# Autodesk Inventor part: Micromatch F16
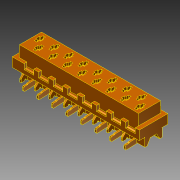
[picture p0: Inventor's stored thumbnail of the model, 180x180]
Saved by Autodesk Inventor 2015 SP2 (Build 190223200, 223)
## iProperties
Created: 2015-08
Part Number: Micromatch F16
Material: Allgemein
Document SubType Name: Modeling
Designer: rYan
Density: 1 g/cm^3
Appearance: Vorgabe
Author: workeradm
Title: c-1-188275-6-u-3d.igs
Organization: Unknown
Description: PTC IGES file: c-1-188275-6-u-3d.igs
Sending System: Pro/ENGINEER by Parametric Technology Corporation
Preprocessor: 2010430
Minimum Resolution: 0.002508
Sending System Product ID: C-1-188275-6
Receiving System Product ID: C-1-188275-6
Sent Units: Millimeter
Translation Standard: USPRO/IPO100 IGES 5.2
Author: rYan
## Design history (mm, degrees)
node "c-1-188275-6-u-3d1"
feature "Zusammengesetzt1"
node "Fläche1"
